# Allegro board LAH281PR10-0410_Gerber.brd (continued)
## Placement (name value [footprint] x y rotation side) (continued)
CN178  10U_0402_6.3V6M  [C_0402]  329.25 13.19 0 bottom
CN179  330U_D2E_6.3VM_R25M  [C_D2E]  311.33 15.48 180 bottom
CN180  0.22U_0201_6.3V6K  [C_0201]  381.94 12.8 270 bottom
CN181  0.22U_0201_6.3V6K  [C_0201]  381.05 12.8 270 bottom
CN182  0.22U_0201_6.3V6K  [C_0201]  378.89 12.8 270 bottom
CN183  0.22U_0201_6.3V6K  [C_0201]  378 12.8 270 bottom
CN184  0.22U_0201_6.3V6K  [C_0201]  375.97 12.8 270 bottom
CN185  0.22U_0201_6.3V6K  [C_0201]  375.08 12.8 270 bottom
CN186  0.22U_0201_6.3V6K  [C_0201]  372.92 12.8 270 bottom
CN187  0.22U_0201_6.3V6K  [C_0201]  372.03 12.8 270 bottom
CN188  10U_0402_6.3V6M  [C_0402]  360.75 9.84 90 top
CN189  10U_0402_6.3V6M  [C_0402]  361.64 9.84 90 top
CN190  0.01U_0402_16V7K  [C_0402]  364.36 10.81 0 top
CN191  0.01U_0402_16V7K  [C_0402]  367.47 10.65 180 top
CN192  0.1U_0201_10V6K  [C_0201]  355.55 9.16 180 bottom
CN193  330U_D2E_6.3VM_R25M  [C_D2E]  359.44 5.65 180 bottom
CN194  0.22U_0201_6.3V6K  [C_0201]  315.64 55.05 0 bottom
CN195  0.22U_0201_6.3V6K  [C_0201]  315.64 54.16 0 bottom
CN196  0.22U_0201_6.3V6K  [C_0201]  315.64 52.05 0 bottom
CN197  0.22U_0201_6.3V6K  [C_0201]  315.64 51.16 0 bottom
CN198  0.22U_0201_6.3V6K  [C_0201]  315.64 49.05 0 bottom
CN199  0.22U_0201_6.3V6K  [C_0201]  315.64 48.16 0 bottom
CN200  0.22U_0201_6.3V6K  [C_0201]  315.64 46.05 0 bottom
CN201  0.22U_0201_6.3V6K  [C_0201]  315.64 45.16 0 bottom
CN202  10U_0402_6.3V6M  [C_0402]  329.12 58.05 0 bottom
CN203  0.01U_0402_16V7K  [C_0402]  328.67 37.73 0 bottom
CN204  0.01U_0402_16V7K  [C_0402]  328.67 38.62 0 bottom
CN205  0.1U_0201_10V6K  [C_0201]  318.05 64.22 90 bottom
CN206  10U_0402_6.3V6M  [C_0402]  328.67 39.51 0 bottom
CN207  330U_D2E_6.3VM_R25M  [C_D2E]  314.78 64.78 90 bottom
CN208  0.22U_0201_6.3V6K  [C_0201]  137 100.82 270 bottom
CN209  0.22U_0201_6.3V6K  [C_0201]  136.11 100.82 270 bottom
CN210  0.22U_0201_6.3V6K  [C_0201]  133.98 100.82 270 bottom
CN211  0.22U_0201_6.3V6K  [C_0201]  133.09 100.82 270 bottom
CN212  0.22U_0201_6.3V6K  [C_0201]  131.49 100.82 270 bottom
CN213  0.22U_0201_6.3V6K  [C_0201]  130.6 100.82 270 bottom
CN214  0.22U_0201_6.3V6K  [C_0201]  129.11 100.64 270 bottom
CN215  0.22U_0201_6.3V6K  [C_0201]  128.51 100.62 270 bottom
CN216  10U_0402_6.3V6M  [C_0402]  120.02 87.37 270 bottom
CN217  330U_D2E_6.3VM_R25M  [C_D2E]  147.84 91.87 90 bottom
CN218  10U_0402_6.3V6M  [C_0402]  142.06 89.68 270 bottom
CN219  0.01U_0402_16V7K  [C_0402]  119.01 87.37 270 bottom
CN220  0.01U_0402_16V7K  [C_0402]  120.91 87.37 270 bottom
CN221  0.1U_0201_10V6K  [C_0201]  121.69 87.46 270 bottom
CN276  0.1U_0201_10V6K  [C_0201]  329.94 33.43 0 bottom
CN277  0.01U_0402_16V7K  [C_0402]  329.89 30.89 0 bottom
CN279  0.01U_0402_16V7K  [C_0402]  329.89 31.8 0 bottom
CN280  0.1U_0201_10V6K  [C_0201]  329.23 26.78 0 bottom
CN281  10U_0402_6.3V6M  [C_0402]  329.35 26.03 0 bottom
CN282  0.01U_0402_16V7K  [C_0402]  329.35 25.12 0 bottom
CN283  0.1U_0201_10V6K  [C_0201]  382.47 10.47 0 top
CN285  0.01U_0402_16V7K  [C_0402]  385.57 10.63 0 top
CN286  0.01U_0402_16V7K  [C_0402]  384.75 10.64 180 top
CN287  0.1U_0201_10V6K  [C_0201]  378.38 10.57 90 top
CN288  0.01U_0402_16V7K  [C_0402]  379.09 10.64 0 top
CN289  10U_0402_6.3V6M  [C_0402]  376.53 10.63 180 top
CN295  0.1U_0201_10V6K  [C_0201]  329.22 58.82 0 bottom
CN297  0.01U_0402_16V7K  [C_0402]  329.12 56.28 0 bottom
CN298  0.01U_0402_16V7K  [C_0402]  329.12 57.16 0 bottom
CN299  0.1U_0201_10V6K  [C_0201]  329.94 51.27 0 bottom
CN300  10U_0402_6.3V6M  [C_0402]  329.78 52.92 0 bottom
CN301  0.01U_0402_16V7K  [C_0402]  329.78 52.03 0 bottom
CN306  0.1U_0201_10V6K  [C_0201]  136.89 91.38 0 top
CN309  0.01U_0402_16V7K  [C_0402]  140.03 87.72 270 bottom
CN310  0.01U_0402_16V7K  [C_0402]  136.83 92.12 0 top
CN311  0.1U_0201_10V6K  [C_0201]  139.27 87.68 270 bottom
CN312  0.01U_0402_16V7K  [C_0402]  136.83 93.03 0 top
CN313  10U_0402_6.3V6M  [C_0402]  141.04 87.72 270 bottom
CR200  5P_0402_50V8C  [C_0402]  14.88 9.96 270 bottom
CR203  0.22U_0201_6.3V6K  [C_0201]  25.96 19.1 180 bottom
CR204  0.22U_0201_6.3V6K  [C_0201]  23.87 13.98 180 bottom
CR205  0.22U_0201_6.3V6K  [C_0201]  25.96 18.21 180 bottom
CR206  0.22U_0201_6.3V6K  [C_0201]  23.9 13.1 180 bottom
CR214  0.1U_0201_25V6K  [C_0201]  11.83 25.13 270 bottom
CR215  10U_0402_6.3V6M  [C_0402]  10.92 24.25 90 bottom
CR217  0.1U_0201_10V6K  [C_0201]  16.04 21.64 0 bottom
CR218  22U_0603_6.3V6M  [C_0603]  15.14 21.67 90 bottom
CR219  100P_0402_50V8J  [C_0402]  24.68 14.9 90 bottom
CR220  1U_0201_6.3V6M  [C_0201]  25.42 15.31 90 bottom
CR221  0.1U_0201_10V6K  [C_0201]  26 15.9 270 bottom
CR222  0.1U_0201_10V6K  [C_0201]  20.13 10.01 0 bottom
CR223  4.7U_0402_6.3V6M  [C_0402]  21.14 10.93 180 bottom
CR224  0.1U_0201_25V6K  [C_0201]  32.2 25.67 180 bottom
CR225  4.7U_0402_6.3V6M  [C_0402]  32.34 26.48 180 bottom
CR227  0.1U_0201_25V6K  [C_0201]  14.02 26.06 180 bottom
CR228  4.7U_0402_6.3V6M  [C_0402]  13.99 25.14 180 bottom
CR229  1U_0201_6.3V6M  [C_0201]  22.94 11.52 90 bottom
CR230  0.1U_0201_10V6K  [C_0201]  22.38 12.12 270 bottom
CR234  0.1U_0201_10V6K  [C_0201]  18.01 9.29 180 bottom
CR235  10U_0402_6.3V6M  [C_0402]  18.26 10.04 180 bottom
CR236  0.1U_0201_25V6K  [C_0201]  12.6 8.49 270 bottom
CR237  100P_0402_50V8J  [C_0402]  24.01 19.29 180 bottom
CR238  1U_0201_6.3V6M  [C_0201]  24.59 20.03 180 bottom
CR239  0.1U_0201_10V6K  [C_0201]  24.57 20.74 0 bottom
CR240  100P_0402_50V8J  [C_0402]  10.75 14.59 0 bottom
CR241  1U_0201_6.3V6M  [C_0201]  10.79 15.33 0 bottom
CR242  0.1U_0201_10V6K  [C_0201]  11.39 15.9 180 bottom
CR244  1U_0201_10V6M  [C_0201]  14.14 8.96 90 bottom
CR245  1U_0201_10V6M  [C_0201]  22.58 21.45 180 bottom
CR246  0.1U_0201_25V6K  [C_0201]  22.58 22.37 180 bottom
CR247  0.1U_0201_10V6K  [C_0201]  19.7 21.05 0 bottom
CR248  4.7U_0402_6.3V6M  [C_0402]  20.75 21.96 180 bottom
CR249  100P_0402_50V8J  [C_0402]  25.89 17.22 180 bottom
CR250  1U_0201_6.3V6M  [C_0201]  24.15 17.56 270 bottom
CR251  0.1U_0201_10V6K  [C_0201]  23.58 16.98 90 bottom
CR252  100P_0402_50V8J  [C_0402]  10.78 17.9 0 bottom
CR253  1U_0201_6.3V6M  [C_0201]  10.82 17.14 0 bottom
CR254  0.1U_0201_10V6K  [C_0201]  11.4 16.5 180 bottom
CR255  1U_0201_10V6M  [C_0201]  29.37 19.13 0 bottom
CR256  0.1U_0201_25V6K  [C_0201]  29.74 13.48 180 bottom
CT1  0.1U_0201_10V6K  [C_0201]  48.17 42.56 0 top
CT2  0.22U_0201_6.3V6K  [C_0201]  44.42 39.45 270 bottom
CT3  0.22U_0201_6.3V6K  [C_0201]  45.03 39.46 270 bottom
CT4  0.22U_0201_6.3V6K  [C_0201]  41.93 39.46 270 bottom
CT5  0.22U_0201_6.3V6K  [C_0201]  42.56 39.46 270 bottom
CT6  0.22U_0201_6.3V6K  [C_0201]  43.2 38.88 90 bottom
CT7  0.22U_0201_6.3V6K  [C_0201]  43.83 38.88 90 bottom
CT8  0.22U_0201_6.3V6K  [C_0201]  40.66 38.88 90 bottom
CT9  0.22U_0201_6.3V6K  [C_0201]  41.29 38.88 90 bottom
CT10  0.22U_0201_6.3V6K  [C_0201]  44.19 50.66 0 bottom
CT11  0.22U_0201_6.3V6K  [C_0201]  44.19 50.02 0 bottom
CT12  0.22U_0201_6.3V6K  [C_0201]  44.23 49.29 0 bottom
CT13  0.22U_0201_6.3V6K  [C_0201]  44.23 48.66 0 bottom
CT14  0.22U_0201_6.3V6K  [C_0201]  44.22 48.01 0 bottom
CT15  0.22U_0201_6.3V6K  [C_0201]  44.22 47.38 0 bottom
CT16  0.22U_0201_6.3V6K  [C_0201]  44.22 46.69 0 bottom
CT17  0.22U_0201_6.3V6K  [C_0201]  44.22 46.06 0 bottom
CT18  0.22U_0201_6.3V6K  [C_0201]  37.54 54.97 90 bottom
CT19  0.22U_0201_6.3V6K  [C_0201]  36.9 54.97 90 bottom
CT20  20P_0402_50V8  [C_0402]  31.5 38.6 0 bottom
CT21  20P_0402_50V8  [C_0402]  29.75 38.57 90 bottom
CT67  1U_0201_10V6M  [C_0201]  26.45 55.7 0 bottom
CT68  47U_0603_6.3V6M  [C_0603]  26.37 56.81 0 bottom
CT69  47U_0603_6.3V6M  [C_0603]  26.37 58.59 0 bottom
CT91  0.47U_0201_25V6M  [C_0201]  11.13 52.47 0 bottom
CT95  0.22U_0201_6.3V6K  [C_0201]  30.39 43.65 180 bottom
CT96  0.22U_0201_6.3V6K  [C_0201]  30.39 44.24 180 bottom
CT97  0.22U_0201_6.3V6K  [C_0201]  30.39 45.55 180 bottom
CT98  0.22U_0201_6.3V6K  [C_0201]  30.39 44.96 180 bottom
CT101  0.47U_0201_25V6M  [C_0201]  11.13 52.47 0 top
CT102  0.47U_0201_25V6M  [C_0201]  11.15 55.96 0 bottom
CT109  0.47U_0201_25V6M  [C_0201]  11.15 55.96 0 top
CT123  0.22U_0201_6.3V6K  [C_0201]  39.39 39.46 270 bottom
CT124  0.22U_0201_6.3V6K  [C_0201]  40.02 39.46 270 bottom
CT125  0.22U_0201_6.3V6K  [C_0201]  37.48 39.46 270 bottom
CT126  0.22U_0201_6.3V6K  [C_0201]  36.85 39.46 270 bottom
CT127  0.22U_0201_6.3V6K  [C_0201]  38.75 38.88 90 bottom
CT128  0.22U_0201_6.3V6K  [C_0201]  38.12 38.88 90 bottom
CT129  0.22U_0201_6.3V6K  [C_0201]  36.21 38.88 90 bottom
CT130  0.22U_0201_6.3V6K  [C_0201]  35.58 38.88 90 bottom
CT178  0.22U_0201_6.3V6K  [C_0201]  38.81 54.97 90 bottom
CT179  0.22U_0201_6.3V6K  [C_0201]  33.33 54.32 90 bottom
CT180  0.22U_0201_6.3V6K  [C_0201]  30.59 54.75 180 bottom
CT181  0.22U_0201_6.3V6K  [C_0201]  33.92 54.31 90 bottom
CT182  0.22U_0201_6.3V6K  [C_0201]  34.55 54.31 90 bottom
CT183  0.22U_0201_6.3V6K  [C_0201]  30.59 55.51 180 bottom
CT184  0.22U_0201_6.3V6K  [C_0201]  38.17 54.97 90 bottom
CT185  0.22U_0201_6.3V6K  [C_0201]  32.69 54.32 90 bottom
CT186  0.22U_0201_6.3V6K  [C_0201]  30.07 53.3 180 bottom
CT187  0.22U_0201_6.3V6K  [C_0201]  30.08 54 180 bottom
CT189  12P_0402_50V8J  [C_0402]  9.93 45.86 180 bottom
CT190  82P_0402_50V8J  [C_0402]  9.93 46.75 180 bottom
CT237  0.1U_0201_10V6K  [C_0201]  118.15 64.66 0 top
CT300  1U_0201_6.3V6M  [C_0201]  35.83 44.6 180 top
CT301  1U_0201_6.3V6M  [C_0201]  34.82 42.34 270 top
CT302  1U_0201_6.3V6M  [C_0201]  33.23 45.4 180 top
CT303  1U_0201_6.3V6M  [C_0201]  40.47 49.19 0 top
CT305  1U_0201_6.3V6M  [C_0201]  34.99 46.56 180 top
CT306  1U_0201_6.3V6M  [C_0201]  35.85 48.53 0 top
CT307  1U_0201_6.3V6M  [C_0201]  37.58 49.24 180 top
CT308  1U_0201_6.3V6M  [C_0201]  34.99 47.19 180 top
CT309  1U_0201_6.3V6M  [C_0201]  36.99 47.13 0 top
CT310  1U_0201_6.3V6M  [C_0201]  37.65 48.45 180 top
CT311  1U_0201_6.3V6M  [C_0201]  39.47 47.65 270 top
CT314  1U_0201_6.3V6M  [C_0201]  34.98 45.82 180 top
CT315  1U_0201_6.3V6M  [C_0201]  38.3 49.8 270 top
CT316  1U_0201_6.3V6M  [C_0201]  38.89 47.25 90 top
CT317  1U_0201_6.3V6M  [C_0201]  38.94 45.95 90 top
CT318  1U_0201_6.3V6M  [C_0201]  35.34 47.77 0 top
CT319  1U_0201_6.3V6M  [C_0201]  36.31 46.62 180 top
CT320  1U_0201_6.3V6M  [C_0201]  32.55 49.8 0 top
CT321  1U_0201_6.3V6M  [C_0201]  39.8 45.16 90 top
CT322  1U_0201_6.3V6M  [C_0201]  40.9 46.55 180 top
CT323  10U_0402_6.3V6M  [C_0402]  32.92 53.35 180 top
CT324  10U_0402_6.3V6M  [C_0402]  32.92 51.58 180 top
CT325  10U_0402_6.3V6M  [C_0402]  32.92 50.69 180 top
CT326  10U_0402_6.3V6M  [C_0402]  32.92 52.47 180 top
CT327  1U_0201_6.3V6M  [C_0201]  37.72 53.01 90 top
CT328  1U_0201_6.3V6M  [C_0201]  33.99 52.6 270 top
CT329  10U_0402_6.3V6M  [C_0402]  33.04 47.64 180 top
CT330  10U_0402_6.3V6M  [C_0402]  33.04 46.75 180 top
CT331  1U_0201_6.3V6M  [C_0201]  33.89 48.53 270 top
CT332  1U_0201_6.3V6M  [C_0201]  33.01 48.53 180 top
CT333  1U_0201_6.3V6M  [C_0201]  36.39 49.2 180 top
CT334  47U_0603_6.3V6M  [C_0603]  31.75 59.52 270 bottom
CT335  47U_0603_6.3V6M  [C_0603]  30.54 59.53 270 bottom
CT336  47U_0603_6.3V6M  [C_0603]  29.33 59.53 270 bottom
CT337  10U_0402_6.3V6M  [C_0402]  38.2 42.53 270 top
CT338  1U_0201_6.3V6M  [C_0201]  37.67 45.82 90 top
CT339  1U_0201_6.3V6M  [C_0201]  37.75 43.37 0 top
CT340  1U_0201_6.3V6M  [C_0201]  37.07 43.32 180 top
CT341  1U_0201_6.3V6M  [C_0201]  37.07 42.71 180 top
CT342  0.1U_0201_10V6K  [C_0201]  23.21 38.64 0 bottom
CT343  1U_0201_6.3V6M  [C_0201]  14.67 34.64 180 bottom
CT344  0.1U_0201_10V6K  [C_0201]  26.54 31.8 0 bottom
CT345  0.1U_0201_10V6K  [C_0201]  26.54 31.24 0 bottom
CT346  1U_0201_6.3V6M  [C_0201]  26.54 32.36 0 bottom
CT347  0.1U_0201_10V6K  [C_0201]  19.24 26.94 180 bottom
CT348  1U_0201_10V6M  [C_0201]  23.95 26.71 90 bottom
CT349  1U_0201_6.3V6M  [C_0201]  19.24 27.83 180 bottom
CT350  0.1U_0201_10V6K  [C_0201]  20.23 38.5 0 bottom
CT351  390P_0402_50V7K  [C_0402]  24.7 39.11 270 bottom
CT352  390P_0402_50V7K  [C_0402]  15.11 36.72 180 bottom
CT353  390P_0402_50V7K  [C_0402]  26.82 37.43 180 bottom
CT354  390P_0402_50V7K  [C_0402]  11.96 35.19 180 bottom
CT355  10U_0603_10V6M  [C_0603]  37.79 21.03 270 top
CT356  1U_0201_10V6M  [C_0201]  36.14 20.75 270 top
CT357  10U_0603_10V6M  [C_0603]  42.77 21.73 270 top
CT358  1U_0201_10V6M  [C_0201]  41.73 21.26 270 top
CT359  0.22U_0201_6.3V6K  [C_0201]  30.31 47.74 180 bottom
CT360  0.22U_0201_6.3V6K  [C_0201]  30.31 48.33 180 bottom
CT361  0.47U_0201_25V6M  [C_0201]  11.44 67.48 315 bottom
CT362  0.47U_0201_25V6M  [C_0201]  11.44 67.48 315 top
CT363  0.47U_0201_25V6M  [C_0201]  12.5 71.4 315 bottom
CT364  0.47U_0201_25V6M  [C_0201]  12.5 71.4 315 top
CT365  0.22U_0201_6.3V6K  [C_0201]  29.77 49.22 180 bottom
CT366  0.22U_0201_6.3V6K  [C_0201]  29.77 49.85 180 bottom
CT367  12P_0402_50V8J  [C_0402]  21.85 68.34 45 bottom
CT368  82P_0402_50V8J  [C_0402]  21.21 68.97 45 bottom
CT370  0.1U_0201_10V6K  [C_0201]  34.34 21.22 180 bottom
CT371  0.1U_0201_10V6K  [C_0201]  41.58 19.06 180 top
CT372  1U_0201_10V6M  [C_0201]  42.22 17.22 90 top
CT373  1U_0201_10V6M  [C_0201]  43.5 18.33 180 top
CT374  1000P_0402_50V7K  [C_0402]  48.52 20.59 180 top
CT375  0.01U_0402_16V7K  [C_0402]  43.55 13.87 270 top
CT376  0.1U_0201_25V6K  [C_0201]  44.43 15.51 90 top
CT377  0.1U_0201_10V6K  [C_0201]  40.61 24.81 180 bottom
CT378  1000P_0201_25V7K  [C_0201]  38.86 26.09 90 bottom
CT379  0.1U_0201_10V6K  [C_0201]  47.6 23.54 0 bottom
CT380  1000P_0201_25V7K  [C_0201]  45.07 26.65 90 bottom
CT383  0.1U_0201_10V6K  [C_0201]  40.05 24.04 0 bottom
CT384  0.1U_0201_10V6K  [C_0201]  47.27 25.5 270 bottom
CT389  0.1U_0201_10V6K  [C_0201]  118.37 61.58 270 top
CV1  0.1U_0201_10V6K  [C_0201]  126.31 133.47 270 top
CV2  0.1U_0201_10V6K  [C_0201]  127.2 133.47 270 top
CV3  0.1U_0201_10V6K  [C_0201]  128.62 133.49 270 top
CV4  0.1U_0201_10V6K  [C_0201]  129.51 133.49 270 top
CV5  0.1U_0201_10V6K  [C_0201]  130.63 133.47 270 top
CV6  0.1U_0201_10V6K  [C_0201]  131.52 133.47 270 top
CV13  1U_0603_50V6K  [C_0603]  141.17 135.52 270 top
CV14  0.01U_0402_50V7K  [C_0402]  141.69 137.04 180 top
CV15  0.1U_0402_50V7K  [C_0402]  142.59 131.59 180 top
CV16  10U_0402_6.3V6M  [C_0402]  110.93 148.99 0 bottom
CV20  0.1U_0201_25V6K  [C_0201]  113.33 119.78 180 bottom
CV60  0.01U_0402_16V7K  [C_0402]  304.06 81.42 180 bottom
CV61  0.01U_0402_16V7K  [C_0402]  294.26 81.68 0 bottom
CV62  0.1U_0201_25V6K  [C_0201]  304.06 78.12 180 bottom
CV63  0.1U_0201_25V6K  [C_0201]  296.82 77.74 180 bottom
CV64  0.1U_0201_25V6K  [C_0201]  294.84 79.21 270 bottom
CV65  0.1U_0201_10V6K  [C_0201]  296.06 74.6 90 top
CV66  0.1U_0201_10V6K  [C_0201]  296.95 74.6 90 top
CV67  0.1U_0201_10V6K  [C_0201]  297.89 74.6 90 top
CV68  0.1U_0201_10V6K  [C_0201]  298.78 74.6 90 top
CV69  0.1U_0201_10V6K  [C_0201]  299.74 74.63 90 top
CV70  0.1U_0201_10V6K  [C_0201]  300.63 74.63 90 top
CV71  0.1U_0201_10V6K  [C_0201]  301.6 74.63 90 top
CV72  0.1U_0201_10V6K  [C_0201]  302.49 74.65 90 top
CV73  0.1U_0201_10V6K  [C_0201]  305.76 77.66 90 top
CV74  0.1U_0201_10V6K  [C_0201]  306.65 77.66 90 top
CV75  2.2U_0402_6.3V6M  [C_0402]  303.43 75.54 270 top
CV427  0.22U_0201_6.3V6K  [C_0201]  237.55 77.73 270 bottom
CV428  0.22U_0201_6.3V6K  [C_0201]  236.64 77.73 270 bottom
CV429  0.22U_0201_6.3V6K  [C_0201]  238.73 75.9 270 bottom
CV430  0.22U_0201_6.3V6K  [C_0201]  237.83 75.9 270 bottom
CV431  0.22U_0201_6.3V6K  [C_0201]  239.8 77.85 270 bottom
CV432  0.22U_0201_6.3V6K  [C_0201]  238.91 77.85 270 bottom
CV433  0.22U_0201_6.3V6K  [C_0201]  240.01 75.14 270 bottom
CV434  0.22U_0201_6.3V6K  [C_0201]  240.9 75.14 270 bottom
CV435  0.22U_0201_6.3V6K  [C_0201]  242.01 77.56 270 bottom
CV436  0.22U_0201_6.3V6K  [C_0201]  241.12 77.56 270 bottom
CV437  0.22U_0201_6.3V6K  [C_0201]  242.26 75.15 270 bottom
CV438  0.22U_0201_6.3V6K  [C_0201]  243.15 75.15 270 bottom
CV439  0.22U_0201_6.3V6K  [C_0201]  244.29 77.18 270 bottom
CV440  0.22U_0201_6.3V6K  [C_0201]  243.41 77.18 270 bottom
CV441  0.22U_0201_6.3V6K  [C_0201]  244.55 74.39 270 bottom
CV442  0.22U_0201_6.3V6K  [C_0201]  245.44 74.39 270 bottom
CV443  0.22U_0201_6.3V6K  [C_0201]  246.83 74.39 270 bottom
CV444  0.22U_0201_6.3V6K  [C_0201]  247.72 74.39 270 bottom
CV445  0.22U_0201_6.3V6K  [C_0201]  245.69 76.58 270 bottom
CV446  0.22U_0201_6.3V6K  [C_0201]  246.6 76.58 270 bottom
CV447  0.22U_0201_6.3V6K  [C_0201]  247.98 76.55 270 bottom
CV448  0.22U_0201_6.3V6K  [C_0201]  248.87 76.55 270 bottom
CV449  0.22U_0201_6.3V6K  [C_0201]  250.01 74.51 270 bottom
CV450  0.22U_0201_6.3V6K  [C_0201]  249.12 74.51 270 bottom
CV451  0.22U_0201_6.3V6K  [C_0201]  250.26 76.55 270 bottom
CV452  0.22U_0201_6.3V6K  [C_0201]  251.15 76.55 270 bottom
CV453  0.22U_0201_6.3V6K  [C_0201]  253.18 74.64 270 bottom
CV454  0.22U_0201_6.3V6K  [C_0201]  254.07 74.64 270 bottom
CV455  0.22U_0201_6.3V6K  [C_0201]  251.41 74.64 270 bottom
CV456  0.22U_0201_6.3V6K  [C_0201]  252.3 74.64 270 bottom
CV457  0.22U_0201_6.3V6K  [C_0201]  255.9 75.61 270 bottom
CV458  0.22U_0201_6.3V6K  [C_0201]  255.01 75.61 270 bottom
CV805  0.1U_0201_16V6K  [C_0201]  236.57 92.79 0 bottom
CV806  10U_0402_6.3V6M  [C_0402]  252.21 84.05 180 top
CV809  0.1U_0201_10V6K  [C_0201]  291.79 77.87 90 bottom
CV810  0.1U_0201_10V6K  [C_0201]  286 84.61 0 bottom
CV811  0.1U_0201_10V6K  [C_0201]  279.51 82.56 180 bottom
CV812  1000P_0402_50V7K  [C_0402]  287.26 76.59 180 bottom
CV813  4.7U_0402_6.3V6M  [C_0402]  150.9 123.59 180 top
CV814  0.1U_0201_10V6K  [C_0201]  149.93 117.68 90 bottom
CV815  0.1U_0201_10V6K  [C_0201]  160.08 119.33 90 bottom
CV816  0.1U_0201_10V6K  [C_0201]  161.37 117.51 0 top
CV817  0.1U_0201_10V6K  [C_0201]  156.47 121.85 270 bottom
CV818  2.2U_0402_6.3V6M  [C_0402]  152.81 125.77 270 top
CV819  0.1U_0201_10V6K  [C_0201]  155.16 113.11 90 top
CV820  0.1U_0201_10V6K  [C_0201]  156.05 113.11 90 top
CV821  0.1U_0201_10V6K  [C_0201]  156.69 110.82 90 top
CV822  0.1U_0201_10V6K  [C_0201]  157.58 110.82 90 top
CV823  0.1U_0201_10V6K  [C_0201]  158.03 113.24 90 top
CV824  0.1U_0201_10V6K  [C_0201]  158.97 113.24 90 top
CV825  0.1U_0201_10V6K  [C_0201]  159.53 110.95 90 top
CV826  0.1U_0201_10V6K  [C_0201]  160.42 110.95 90 top
CV827  0.1U_0201_10V6K  [C_0201]  163.37 122.2 180 top
CV828  0.1U_0201_10V6K  [C_0201]  163.37 121.31 180 top
CV829  0.1U_0201_10V6K  [C_0201]  149.53 113.11 90 top
CV830  0.1U_0201_10V6K  [C_0201]  150.41 113.11 90 top
CV831  0.1U_0201_10V6K  [C_0201]  150.59 110.7 90 top
CV832  0.1U_0201_10V6K  [C_0201]  151.48 110.7 90 top
CV833  0.1U_0201_10V6K  [C_0201]  152.34 112.98 90 top
CV834  0.1U_0201_10V6K  [C_0201]  153.26 112.98 90 top
CV835  0.1U_0201_10V6K  [C_0201]  153.64 110.7 90 top
CV836  0.1U_0201_10V6K  [C_0201]  154.53 110.7 90 top
CV837  0.1U_0201_10V6K  [C_0201]  163.37 120.42 180 top
CV838  0.1U_0201_10V6K  [C_0201]  163.37 119.53 180 top
CV839  82P_0402_50V8J  [C_0402]  141.68 132.54 0 top
CV840  82P_0402_50V8J  [C_0402]  113.94 116.28 180 top
CV841  22P_0402_50V8J  [C_0402]  113.94 115.33 180 top
CV842  100P_0402_50V8J  [C_0402]  125.98 110 0 top
CV843  100P_0402_50V8J  [C_0402]  126.95 111.32 90 top
CV844  0.1U_0201_10V6K  [C_0201]  163.98 125.16 270 top
CV845  0.1U_0201_10V6K  [C_0201]  132.53 133.47 270 top
CV846  0.1U_0201_10V6K  [C_0201]  133.42 133.47 270 top
CV847  0.1U_0201_10V6K  [C_0201]  134.44 133.47 270 top
CV848  0.1U_0201_10V6K  [C_0201]  135.33 133.47 270 top
CV849  0.1U_0402_50V7K  [C_0402]  114.82 115.42 90 top
CV851  10P_0402_50V8J  [C_0402]  112.65 120.66 0 bottom
CV852  82P_0402_50V8J  [C_0402]  117.09 120.54 0 bottom
CV853  2.2P_0402_50V8C  [C_0402]  113.56 121.55 180 bottom
CV854  4.7U_0402_6.3V6M  [C_0402]  63.32 56.33 90 top
CV855  0.1U_0201_10V6K  [C_0201]  61.36 56.56 90 top
CV856  0.1U_0201_10V6K  [C_0201]  62.26 56.56 90 top
CV857  0.01U_0402_16V7K  [C_0402]  59.56 56.38 90 top
CV858  0.01U_0402_16V7K  [C_0402]  60.46 56.39 90 top
CV860  0.22U_0201_6.3V6K  [C_0201]  60.87 53.61 0 bottom
CV861  0.22U_0201_6.3V6K  [C_0201]  60.87 52.97 0 bottom
CV862  0.22U_0201_6.3V6K  [C_0201]  60.87 52.34 0 bottom
CV863  0.22U_0201_6.3V6K  [C_0201]  60.87 51.7 0 bottom
CV864  0.22U_0201_6.3V6K  [C_0201]  60.36 50.94 0 bottom
CV865  0.22U_0201_6.3V6K  [C_0201]  60.36 50.31 0 bottom
CV866  0.22U_0201_6.3V6K  [C_0201]  61.63 49.93 0 bottom
CV867  0.22U_0201_6.3V6K  [C_0201]  61.63 49.29 0 bottom
CV868  0.22U_0201_6.3V6K  [C_0201]  60.36 48.91 0 bottom
CV869  0.22U_0201_6.3V6K  [C_0201]  60.36 48.27 0 bottom
CV870  0.22U_0201_6.3V6K  [C_0201]  60.23 47.13 0 bottom
CV871  0.22U_0201_6.3V6K  [C_0201]  60.23 46.5 0 bottom
CV872  0.22U_0201_6.3V6K  [C_0201]  63.41 45.73 0 bottom
CV873  0.22U_0201_6.3V6K  [C_0201]  63.41 45.1 0 bottom
CV874  0.22U_0201_6.3V6K  [C_0201]  60.23 44.72 0 bottom
CV875  0.22U_0201_6.3V6K  [C_0201]  60.23 44.08 0 bottom
CV876  0.1U_0201_10V6K  [C_0201]  55.06 56.95 270 bottom
CV877  0.1U_0201_10V6K  [C_0201]  54.43 56.95 270 bottom
CV878  4.7U_0402_6.3V6M  [C_0402]  68.16 42.14 90 top
CV879  0.1U_0201_10V6K  [C_0201]  67.13 42.33 90 top
CV880  0.1U_0201_10V6K  [C_0201]  69.16 42.33 90 top
CV881  0.01U_0402_16V7K  [C_0402]  68.66 44.5 180 top
CV882  0.01U_0402_16V7K  [C_0402]  69.67 47.69 90 top
CV883  0.22U_0201_6.3V6K  [C_0201]  70.81 45.39 270 top
CV884  0.22U_0201_6.3V6K  [C_0201]  71.45 45.39 270 top
CV885  0.22U_0201_6.3V6K  [C_0201]  72.97 45.77 270 top
CV886  0.22U_0201_6.3V6K  [C_0201]  73.61 45.77 270 top
CV887  0.22U_0201_6.3V6K  [C_0201]  74.24 45.77 270 top
CV888  0.22U_0201_6.3V6K  [C_0201]  74.88 45.77 270 top
CV889  0.22U_0201_6.3V6K  [C_0201]  75.51 45.77 270 top
CV890  0.22U_0201_6.3V6K  [C_0201]  76.15 45.77 270 top
CV891  0.22U_0201_6.3V6K  [C_0201]  76.78 45.77 270 top
CV892  0.22U_0201_6.3V6K  [C_0201]  77.42 45.77 270 top
CV893  0.22U_0201_6.3V6K  [C_0201]  78.18 45.77 270 top
CV894  0.22U_0201_6.3V6K  [C_0201]  78.81 45.77 270 top
CV895  0.22U_0201_6.3V6K  [C_0201]  79.7 45.77 270 top
CV896  0.22U_0201_6.3V6K  [C_0201]  80.34 45.77 270 top
CV897  0.22U_0201_6.3V6K  [C_0201]  80.97 45.77 270 top
CV898  0.22U_0201_6.3V6K  [C_0201]  81.61 45.77 270 top
CV901  0.01U_0402_16V7K  [C_0402]  49.19 41.69 270 bottom
CV902  10U_0402_6.3V6M  [C_0402]  247.65 83.82 180 top
CV903  0.1U_0201_10V6K  [C_0201]  230.87 94.25 180 bottom
CV908  0.1U_0201_10V6K  [C_0201]  62.75 56.56 90 bottom
CV909  0.1U_0201_10V6K  [C_0201]  59.7 42.53 270 bottom
CV910  4.7U_0402_6.3V6M  [C_0402]  63.7 56.53 0 bottom
CV911  0.01U_0402_16V7K  [C_0402]  52.77 48.58 0 top
CV912  0.01U_0402_16V7K  [C_0402]  52.7 54.37 0 top
CV913  0.1U_0201_10V6K  [C_0201]  52.93 53.42 0 top
CV914  4.7U_0402_6.3V6M  [C_0402]  52.7 55.45 0 top
CV915  0.1U_0201_10V6K  [C_0201]  52.8 47.7 0 top
CV916  0.01U_0402_16V7K  [C_0402]  52.53 45.61 0 top
CV917  1U_0201_10V6M  [C_0201]  52.99 44.59 0 top
CV918  0.1U_0201_10V6K  [C_0201]  52.8 46.5 0 top
CV919  4.7U_0402_6.3V6M  [C_0402]  52.67 43.32 0 top
CV920  0.01U_0402_16V7K  [C_0402]  82.93 53.08 0 top
CV921  0.01U_0402_16V7K  [C_0402]  69.1 55.42 180 top
CV922  0.1U_0201_10V6K  [C_0201]  85.89 55.26 0 top
CV923  0.1U_0201_10V6K  [C_0201]  69.07 56.28 180 top
CV924  4.7U_0402_6.3V6M  [C_0402]  86.81 56.39 90 top
CV925  0.01U_0402_16V7K  [C_0402]  82.8 46.24 0 top
CV926  0.01U_0402_16V7K  [C_0402]  82.8 47.13 0 top
CV927  0.1U_0201_10V6K  [C_0201]  71.78 45.79 270 bottom
CV928  4.7U_0402_6.3V6M  [C_0402]  69.75 45.93 270 bottom
CV929  0.1U_0201_10V6K  [C_0201]  70.76 45.79 270 bottom
CV930  0.01U_0402_16V7K  [C_0402]  78.33 56.45 90 top
CV931  0.01U_0402_16V7K  [C_0402]  79.23 56.47 90 top
CV932  0.1U_0201_10V6K  [C_0201]  67.05 56.62 180 bottom
CV933  4.7U_0402_6.3V6M  [C_0402]  68.85 56.15 0 bottom
CV934  0.1U_0201_10V6K  [C_0201]  67.1 57.86 180 bottom
CV935  0.01U_0402_16V7K  [C_0402]  70.09 54.63 270 bottom
CV936  4.7U_0402_6.3V6M  [C_0402]  68.97 54.66 270 bottom
CV937  0.1U_0201_10V6K  [C_0201]  71.9 54.61 270 bottom
CV938  1U_0201_10V6M  [C_0201]  70.99 54.61 270 bottom
CV939  0.1U_0201_10V6K  [C_0201]  58.44 56.16 0 bottom
CV940  1U_0201_10V6M  [C_0201]  58.47 57.05 0 bottom
CV941  0.1U_0201_10V6K  [C_0201]  68.79 47.88 90 top
CV942  1U_0201_10V6M  [C_0201]  67.85 47.88 90 top
CV943  0.1U_0201_10V6K  [C_0201]  67.94 50.43 0 top
CV944  0.1U_0201_10V6K  [C_0201]  67.94 49.54 0 top
CV945  0.1U_0201_10V6K  [C_0201]  56.33 56.95 270 bottom
CV946  0.1U_0201_10V6K  [C_0201]  55.7 56.95 270 bottom
CV947  0.01U_0402_16V7K  [C_0402]  51.22 41.69 270 bottom
CV948  0.1U_0201_10V6K  [C_0201]  50.24 41.39 270 bottom
CV949  0.01U_0402_16V7K  [C_0402]  61.87 56.31 90 bottom
CV950  4.7U_0402_6.3V6M  [C_0402]  50.84 54.6 90 bottom
CV951  0.1U_0201_10V6K  [C_0201]  51.83 54.71 90 bottom
CV952  0.01U_0402_16V7K  [C_0402]  60.99 56.31 90 bottom
CV954  0.1U_0201_25V6K  [C_0201]  136.41 131.59 0 bottom
CV955  82P_0402_50V8J  [C_0402]  155.56 121.97 270 bottom
CV956  82P_0402_50V8J  [C_0402]  248.59 83.82 0 top
CV957  82P_0402_50V8J  [C_0402]  253.24 83.66 0 top
CZ10  0.1U_0201_10V6K  [C_0201]  156.43 102.82 90 bottom
CZ11  0.1U_0201_10V6K  [C_0201]  157.32 102.82 90 bottom
CZ12  0.1U_0201_25V6K  [C_0201]  119.05 101.42 90 bottom
CZ13  0.1U_0201_25V6K  [C_0201]  119.94 101.42 90 bottom
CZ17  0.047U_0201_10V6K  [C_0201]  143.23 116.86 90 bottom
CZ18  0.047U_0201_10V6K  [C_0201]  144.12 116.86 90 bottom
CZ19  33P_0402_50V8J  [C_0402]  163.42 116.54 90 bottom
CZ20  22U_0603_6.3V6M  [C_0603]  165.07 116.55 90 top
CZ21  33P_0402_50V8J  [C_0402]  164.31 116.54 90 bottom
CZ28  0.1U_0201_10V6K  [C_0201]  153.51 99.52 90 bottom
CZ29  0.1U_0201_10V6K  [C_0201]  154.4 99.52 90 bottom
CZ37  1U_0201_10V6M  [C_0201]  122.35 160.96 180 bottom
CZ38  33P_0402_50V8J  [C_0402]  127.96 161.98 0 bottom
CZ39  33P_0402_50V8J  [C_0402]  127.96 160.7 0 bottom
CZ40  33P_0402_50V8J  [C_0402]  124.29 160.96 180 bottom
CZ50  0.1U_0201_25V6K  [C_0201]  144.12 18.81 0 bottom
CZ51  0.1U_0201_10V6K  [C_0201]  145.62 21.39 270 bottom
CZ52  10U_0402_6.3V6M  [C_0402]  146.53 21.65 270 bottom
CZ53  0.1U_0201_10V6K  [C_0201]  136.81 17.67 0 top
CZ54  0.1U_0201_10V6K  [C_0201]  136.81 17.03 0 top
CZ55  10U_0603_10V6M  [C_0603]  137.35 18.56 0 top
CZ56  0.1U_0201_25V6K  [C_0201]  134.34 15.62 0 bottom
CZ57  12P_0402_50V8J  [C_0402]  150.78 23.76 0 bottom
CZ58  68P_0402_50V8J  [C_0402]  150.78 24.65 0 bottom
CZ59  12P_0402_50V8J  [C_0402]  147.71 18.98 0 bottom
CZ60  68P_0402_50V8J  [C_0402]  147.73 19.89 0 bottom
CZ61  0.047U_0201_10V6K  [C_0201]  339.88 47.89 0 top
CZ62  68P_0402_50V8J  [C_0402]  338.15 54.8 90 top
CZ63  68P_0402_50V8J  [C_0402]  335.28 53.48 0 bottom
CZ64  0.1U_0201_10V6K  [C_0201]  337.59 50.88 90 top
CZ66  0.1U_0201_10V6K  [C_0201]  337.5 48.63 0 top
CZ67  0.1U_0201_10V6K  [C_0201]  337.84 50.14 270 top
CZ68  0.1U_0201_10V6K  [C_0201]  337.41 53.08 90 top
CZ69  68P_0402_50V8J  [C_0402]  339.17 51.31 0 top
CZ71  68P_0402_50V8J  [C_0402]  337.18 48.53 0 bottom
CZ72  68P_0402_50V8J  [C_0402]  339.37 49.88 0 top
CZ73  68P_0402_50V8J  [C_0402]  337.56 52.21 0 top
CZ75  10U_0402_6.3V6M  [C_0402]  143.99 17.07 0 bottom
CZ80  10P_0402_50V8J  [C_0402]  29.24 12.24 0 bottom
CZ81  10P_0402_50V8J  [C_0402]  29.14 8.24 0 bottom
CZ82  0.1U_0201_10V6K  [C_0201]  106.91 13.29 90 bottom
CZ90  0.1U_0201_25V6K  [C_0201]  17.65 7.76 0 bottom
CZ91  0.1U_0201_25V6K  [C_0201]  15.59 7.46 180 bottom
CZ92  0.1U_0201_25V6K  [C_0201]  13.2 4.79 270 bottom
CZ93  0.1U_0201_10V6K  [C_0201]  388.33 6.16 180 top
CZ100  1U_0201_10V6M  [C_0201]  278.65 73.27 270 bottom
CZ101  0.1U_0201_10V6K  [C_0201]  273.38 73.08 270 bottom
CZ102  1U_0201_10V6M  [C_0201]  164.06 30.85 180 bottom
CZ105  1U_0201_10V6M  [C_0201]  269.19 79.48 90 top
CZ106  0.1U_0201_10V6K  [C_0201]  272.2 82.31 0 top
CZ120  0.1U_0201_10V6K  [C_0201]  335.46 15.51 180 top
CZ121  470P_0402_50V7K  [C_0402]  336.98 12.84 270 top
CZ129  0.1U_0201_10V6K  [C_0201]  366.51 14.14 180 top
CZ130  470P_0402_50V7K  [C_0402]  365.05 11.81 180 bottom
CZ157  330U_D2E_6.3VM_R25M  [C_D2E]  113.74 112.54 0 top
CZ164  330U_D2E_6.3VM_R25M  [C_D2E]  168.6 117.37 270 top
CZ198  100P_0402_50V8J  [C_0402]  144.71 118.57 0 bottom
CZ199  0.1U_0201_10V6K  [C_0201]  162.84 36.31 180 bottom
CZ200  0.1U_0201_10V6K  [C_0201]  152.41 19.28 270 bottom
CZ218  2.2U_0201_6.3V6M  [C_0201]  99.77 62.02 90 top
CZ505  10U_0402_6.3V6M  [C_0402]  303.73 71.32 180 top
CZ506  10U_0402_6.3V6M  [C_0402]  122.11 77.87 0 top
CZ507  0.1U_0201_25V6K  [C_0201]  122.53 78.95 0 top
CZ508  0.1U_0201_25V6K  [C_0201]  303.58 72.4 180 top
CZ509  0.1U_0201_25V6K  [C_0201]  137.68 130.22 90 bottom
CZ510  10U_0402_6.3V6M  [C_0402]  116.61 115.52 180 top
CZ511  0.1U_0201_25V6K  [C_0201]  117.76 116.28 0 top
CZ512  10P_0402_50V8J  [C_0402]  118.39 115.33 180 top
CZ513  0.1U_0201_10V6K  [C_0201]  297.15 65.1 0 top
CZ514  0.1U_0201_10V6K  [C_0201]  92.3 55.51 0 top
CZ515  470P_0402_50V7K  [C_0402]  92.81 59.15 180 top
CZ516  470P_0402_50V7K  [C_0402]  294.56 68.09 0 top
CZ517  470P_0402_50V7K  [C_0402]  294.56 67.2 0 top
CZ518  0.1U_0201_10V6K  [C_0201]  297.03 69.74 0 top
CZ519  0.1U_0201_10V6K  [C_0201]  370.41 37.44 90 top
CZ520  0.1U_0201_10V6K  [C_0201]  141.59 19.45 180 top
CZ521  470P_0402_50V7K  [C_0402]  142.52 13.98 180 top
CZ522  1000P_0402_50V7K  [C_0402]  370.85 34.04 180 top
CZ523  470P_0402_50V7K  [C_0402]  370.85 34.93 180 top
CZ524  0.1U_0201_10V6K  [C_0201]  369.45 31.8 270 top
CZ525  0.1U_0201_25V6K  [C_0201]  133.45 98.63 0 top
CZ526  0.47U_0402_25V6K  [C_0402]  130.91 87.52 180 top
CZ527  0.1U_0201_10V6K  [C_0201]  396.73 13.93 180 bottom
CZ528  82P_0402_50V8J  [C_0402]  296.92 70.68 0 top
CZ529  82P_0402_50V8J  [C_0402]  296.92 64.25 0 top
CZ530  0.1U_0201_10V6K  [C_0201]  110.46 115.09 90 bottom
CZ531  10U_0402_6.3V6M  [C_0402]  111.21 115.1 90 bottom
CZ532  0.01U_0402_16V7K  [C_0402]  129.32 115.04 90 bottom
CZ533  0.01U_0402_16V7K  [C_0402]  128.43 115.04 90 bottom
CZ534  0.1U_0201_10V6K  [C_0201]  127.7 114.94 90 bottom
CZ535  10U_0402_6.3V6M  [C_0402]  110.96 113.62 180 top
CZ536  0.1U_0201_25V6K  [C_0201]  126.57 101.67 90 bottom
CZ537  0.1U_0201_25V6K  [C_0201]  125.68 101.67 90 bottom
CZ538  0.1U_0201_25V6K  [C_0201]  124.79 101.67 90 bottom
CZ539  0.1U_0201_25V6K  [C_0201]  123.9 101.67 90 bottom
CZ540  0.1U_0201_10V6K  [C_0201]  363.23 12.82 270 bottom
CZ541  100P_0402_50V8J  [C_0402]  357.6 53.3 270 top
CZ542  0.01U_0402_16V7K  [C_0402]  111.4 112.66 180 top
CZ543  0.01U_0402_16V7K  [C_0402]  111.43 111.75 180 top
CZ544  0.1U_0201_25V6K  [C_0201]  274.37 73.48 180 top
CZ545  82P_0402_50V8J  [C_0402]  133.28 97.86 0 top
DA1  AZ5125-02S.R7G_SOT23-3  [AZ5125-02SPR7G_SOT23-3]  391.72 24.65 270 top
DA2  AZ5125-02S.R7G_SOT23-3  [AZ5125-02SPR7G_SOT23-3]  393.8 20.59 90 top
DA3  AZ5123-02S.R7G_SOT23-3  [AZ5123-02SPR7G_SOT23-3]  393.8 16.65 90 top
DA6  AZ5125-02S.R7G_SOT23-3  [AZ5125-02SPR7G_SOT23-3]  345.64 16.33 0 top
DA7  AZ5125-02S.R7G_SOT23-3  [AZ5125-02SPR7G_SOT23-3]  349.61 16.3 0 top
DA8  -  [RB751S-40_SOD523-2]  373.96 27.75 0 top
DE2  -  [RB751S-40_SOD523-2]  144 83.71 0 top
DH1  -  [RB751S-40_SOD523-2]  123.5 15.65 180 top
DH2  -  [RB751S-40_SOD523-2]  121.17 14.12 0 top
DI1  -  [AZ1045-04F_DFN2510P10E-10-9]  389.48 55.89 270 bottom
DI2  -  [PESD5V0U2BT_SOT23-3]  391.51 64.04 90 top
DI3  -  [PESD5V0U2BT_SOT23-3]  391.28 36.73 90 top
DI4  -  [AZ1045-04F_DFN2510P10E-10-9]  111.87 157.32 0 top
DI5  -  [PESD5V0U2BT_SOT23-3]  119.73 159.77 180 top
DI6  -  [AZ1045-04F_DFN2510P10E-10-9]  391.82 43.95 270 bottom
DT1  -  [SDMP0340LAT-7-F_SOT-523-3]  20.98 52.4 90 bottom
DT2  -  [SDMP0340LAT-7-F_SOT-523-3]  19.9 54.12 270 top
DT3  -  [SDMP0340LAT-7-F_SOT-523-3]  15.19 60.17 0 bottom
DT4  AZ4024_02S_R7G_SOT23-3  [PESD24VS2UT_SOT23-3]  14.58 48.02 270 bottom
DT5  AZ5B75-01B.R7G_CSP0603P2Y2  [AZ5B75-01BPR7G_CSP0603P2Y2]  16.76 49.4 270 bottom
DT6  AZ5B75-01B.R7G_CSP0603P2Y2  [AZ5B75-01BPR7G_CSP0603P2Y2]  16.76 50.09 90 bottom
DT7  -  [AZ1045-04F_DFN2510P10E-10-9]  12.26 53.19 90 bottom
DT8  -  [AZ1045-04F_DFN2510P10E-10-9]  13.14 53.19 90 top
DT9  AZ5B75-01B.R7G_CSP0603P2Y2  [AZ5B75-01BPR7G_CSP0603P2Y2]  12.32 57.19 270 bottom
DT10  AZ5B75-01B.R7G_CSP0603P2Y2  [AZ5B75-01BPR7G_CSP0603P2Y2]  12.32 57.89 90 bottom
DT11  -  [AZ1045-04F_DFN2510P10E-10-9]  14.09 66.15 0 bottom
DT12  -  [AZ1045-04F_DFN2510P10E-10-9]  14.09 65.28 0 top
DT13  AZ5B75-01B.R7G_CSP0603P2Y2  [AZ5B75-01BPR7G_CSP0603P2Y2]  16.76 49.4 270 top
DT14  AZ5B75-01B.R7G_CSP0603P2Y2  [AZ5B75-01BPR7G_CSP0603P2Y2]  16.76 50.09 90 top
DT16  -  [SDMP0340LAT-7-F_SOT-523-3]  18.57 60.97 270 top
DT17  AZ5B75-01B.R7G_CSP0603P2Y2  [AZ5B75-01BPR7G_CSP0603P2Y2]  12.32 57.89 90 top
DT18  AZ5B75-01B.R7G_CSP0603P2Y2  [AZ5B75-01BPR7G_CSP0603P2Y2]  12.32 57.19 270 top
DT43  AZ5B75-01B.R7G_CSP0603P2Y2  [AZ5B75-01BPR7G_CSP0603P2Y2]  11.21 64.64 180 bottom
DT44  AZ5B75-01B.R7G_CSP0603P2Y2  [AZ5B75-01BPR7G_CSP0603P2Y2]  11.21 64.64 180 top
DT45  AZ5B75-01B.R7G_CSP0603P2Y2  [AZ5B75-01BPR7G_CSP0603P2Y2]  11.91 64.64 0 top
DT48  AZ5B75-01B.R7G_CSP0603P2Y2  [AZ5B75-01BPR7G_CSP0603P2Y2]  11.91 64.64 0 bottom
DT51  AZ5B75-01B.R7G_CSP0603P2Y2  [AZ5B75-01BPR7G_CSP0603P2Y2]  14.87 73.19 270 bottom
DT52  AZ5B75-01B.R7G_CSP0603P2Y2  [AZ5B75-01BPR7G_CSP0603P2Y2]  14.87 73.89 90 top
DT53  AZ5B75-01B.R7G_CSP0603P2Y2  [AZ5B75-01BPR7G_CSP0603P2Y2]  14.87 73.89 90 bottom
DT54  AZ5B75-01B.R7G_CSP0603P2Y2  [AZ5B75-01BPR7G_CSP0603P2Y2]  14.87 73.19 270 top
DT59  AZ4024_02S_R7G_SOT23-3  [PESD24VS2UT_SOT23-3]  21.99 65.01 135 bottom
DT60  -  [RB520SM-30T2R_EMD2-2]  48.63 25.45 90 top
DT62  -  [RB520SM-30T2R_EMD2-2]  47.43 25.44 90 top
DT63  -  [RB520SM-30T2R_EMD2-2]  48.69 23.47 270 top
DT64  -  [RB520SM-30T2R_EMD2-2]  47.42 23.47 270 top
DT2001  -  [SBR1A20T5-7_SOD523-2-2]  15.78 51.77 0 top
DT2002  -  [SBR1A20T5-7_SOD523-2-2]  14.97 55.77 0 bottom
DT2003  -  [SBR1A20T5-7_SOD523-2-2]  15.1 55.89 0 top
DT2004  -  [SBR1A20T5-7_SOD523-2-2]  15.29 52.59 0 bottom
DT2005  -  [SBR1A20T5-7_SOD523-2-2]  13.6 63.6 270 bottom
DT2006  -  [SBR1A20T5-7_SOD523-2-2]  17.16 64.36 270 bottom
DT2007  -  [SBR1A20T5-7_SOD523-2-2]  17.16 64.3 270 top
DT2008  -  [SBR1A20T5-7_SOD523-2-2]  13.47 63.6 270 top
DV3  -  [BAT54CW_SOT323-3]  117.04 144.54 90 top
DV4  AZ5125-02S.R7G_SOT23-3  [AZ5125-02SPR7G_SOT23-3]  125.19 111.52 90 top
DV32  -  [RB751VM-40TE-17_SOD323-2]  290.52 80.79 180 bottom
DV33  -  [RB751VM-40TE-17_SOD323-2]  291.69 73.7 180 bottom
DV34  -  [RB751VM-40TE-17_SOD323-2]  286.84 80.58 270 bottom
DV35  -  [RB751VM-40TE-17_SOD323-2]  167.73 129.01 90 top
DV36  -  [RB751VM-40TE-17_SOD323-2]  169.39 129.01 90 top
DV37  -  [RB751VM-40TE-17_SOD323-2]  166.08 129.01 90 top
DV38  -  [RB751VM-40TE-17_SOD323-2]  163.05 129.17 180 top
DV39  -  [RB751VM-40TE-17_SOD323-2]  167.76 125.5 270 top
DV40  -  [RB751VM-40TE-17_SOD323-2]  163.05 130.82 180 top
DV41  -  [PESD5V0U2BT_SOT23-3]  125.87 114.7 270 top
DV42  -  [RB751VM-40TE-17_SOD323-2]  115.58 144.7 90 top
DV43  -  [RB751VM-40TE-17_SOD323-2]  223.45 82.12 0 top
DV44  -  [RB751VM-40TE-17_SOD323-2]  230.83 83.07 0 bottom
DZ1  -  [RB751S-40_SOD523-2]  124.86 117.03 270 bottom
DZ2  -  [RB751S-40_SOD523-2]  123.64 117.03 270 bottom
DZ5  -  [RB751S-40_SOD523-2]  147.65 117.94 270 bottom
DZ6  -  [RB751S-40_SOD523-2]  148.85 117.92 270 bottom
DZ8  -  [RB751S-40_SOD523-2]  338.12 46.01 0 top
DZ9  -  [BAT54CW_SOT323-3]  149.15 98.79 270 top
DZ12  -  [RB751S40T1G_SOD523-2]  98.97 63.32 180 top
DZ20  BZX384-B5V6 SC76-2  [RB751V40_SC76-2]  304.75 69.61 180 top
DZ21  BZX384-B5V6 SC76-2  [RB751V40_SC76-2]  120.99 79.42 90 top
FD1  FIDUCIAL MARK~D  [FIDUCIAL_C40M80]  12.39 78.12 0 top
FD2  FIDUCIAL MARK~D  [FIDUCIAL_C40M80]  6.53 19.23 180 bottom
FD3  FIDUCIAL MARK~D  [FIDUCIAL_C40M80]  355.52 19.31 0 top
FD4  FIDUCIAL MARK~D  [FIDUCIAL_C40M80]  359.29 44.87 180 bottom
FD5  FIDUCIAL MARK~D  [FIDUCIAL_C40M80]  279.09 25.14 180 bottom
FD6  FIDUCIAL MARK~D  [FIDUCIAL_C40M80]  156.73 3.66 0 top
FV1  1.5A_65V_T0603FF1500TM  [F_T0603FF1500TM]  134.2 124.13 270 bottom
FZ1  1A_65V_T0603FF1000TM  [F_T0603FF1000TM]  136.64 126.3 180 bottom
FZ2  1A_65V_T0603FF1000TM  [F_T0603FF1000TM]  112.95 143.14 0 top
H1  -  [H_3P2]  392.25 3 0 top
H3  -  [H_3P2]  141.21 121.07 0 top
H4  -  [H_2P8]  109.95 92.8 0 top
H5  -  [H_3P2]  63.25 2.6 0 top
H6  -  [H_2P5]  3.95 46.76 0 top
H7  -  [H_3P7]  263.95 75.27 0 top
H8  -  [H_3P7]  263.95 20.87 0 top
H9  -  [H_3P2]  132.95 172.1 0 top
H11  -  [H_3P2]  295.95 90.8 0 top
H12  -  [H_3P7]  227.85 19.07 0 top
H13  -  [H_3P7]  227.85 76.17 0 top
H14  -  [H_3P2]  403.75 74.03 0 top
H15  -  [H_3P2]  249.95 2.6 0 top
H16  -  [H_2P5]  3.6 62.95 0 top
H17  -  [H_2P8]  324.95 64.8 0 top
H18  -  [H_2P5]  3.95 79.16 0 top
H19  -  [H_2P8]  6.85 41.03 0 top
H20  -  [H_2P0N]  392.25 7 0 top
H21  -  [H_3P2]  120.01 138.36 0 top
H22  -  [H_3P2]  154.48 152.54 0 top
H23  -  [H_2P8X2P0N]  132.97 165.59 328.9 top
JAPS1  ACES_50506-01841-P01  [ACES_50506-01841-P01_18P]  110.97 71.02 270 bottom
JCCG1  ACES_50521-01041-P01  [ACES_50521-01041-P01_10P]  22.33 44.7 180 bottom
JDEG1  JXT_FP241AH-010GAAM  [JXT_FP241AH-010GAAM_10P]  112.38 58.31 270 bottom
JDG1  BELLW_80252-0521  [BELLW_80252-0521_5P-T]  110.4 105.75 90 top
JDGFF1  UNIMI_FBGCAX011  [UNIMI_FBGCAX011_68P-T-S]  239.01 87.52 180 top
JDGFF2  UNIMI_FBGCAX011  [UNIMI_FBGCAX011_68P-T-S]  254.01 87.52 180 top
JDGFF3  UNIMI_FBGCAX011  [UNIMI_FBGCAX011_68P-T-S]  269.01 87.52 180 top
JDGFF4  UNIMI_FBGCAX011  [UNIMI_FBGCAX011_68P-T-S]  284.01 87.52 180 top
JDIMM1  ADDR0208-P001A02  [LOTES_ADDR0208-P001A_260P]  173.67 15.73 270 bottom
JDIMM2  BELLW_80888-2021  [BELLW_80888-2021_260P-T]  181.87 15.73 90 top
JDIMM3  BELLW_80888-2021  [BELLW_80888-2021_260P-T]  187.39 15.72 90 bottom
JDIMM4  ADDR0206-P001A02  [LOTES_ADDR0208-P001A_260P]  195.59 15.73 270 top
JEDP1  ACES_50398-04041-001  [ACES_50398-04041-001_40P]  113.2 118.91 0 top
JESPI  JXT_FP241AH-010GAAM  [JXT_FP241AH-010GAAM_10P]  100.33 15.2 180 bottom
JFAN1  ACES_50271-0040N-001  [ACES_50271-0040N-001_4P]  115.43 74.64 240.6 top
JFAN2  ACES_50271-0040N-001  [ACES_50271-0040N-001_4P]  306.95 73.1 90 top
JHP1  SINGA_2SJ3088-025111F  [SINGA_2SJ3088-025111F_6P-T]  397.75 26 270 top
JIR1  ACES_50228-0067N-001  [ACES_50228-0067N-001_6P]  114.55 132.8 0 top
JKBTP1  CVILU_CF2020FV0RK-NH  [CVILU_CF2020FV0RK-NH_20P]  13.34 3.07 0 top
JLED1  CVILU_CF2006FV0RK-NH  [CVILU_CF2006FV0RK-NH_6P]  400.5 11.15 0 top
JLOM1  SANTA_130456-911  [SANTA_130456-911_13P-T]  142.18 162.92 180 top
JNGFF1  BELLW_80148-4221  [BELLW_80148-4221_67P]  110.75 104.83 0 bottom
JNGFF2  LOTES_APCI0071-P001A  [LOTES_APCI0071-P001A_67P]  145.24 107.01 0 bottom
JNGFF3  BELLW_SD-80159-4221  [BELLW_SD-80159-4221_67P-T]  319.42 32.04 270 bottom
JNGFF4  LOTES_AP-APCI0356-P001A~D  [LOTES_AP-APCI0356-P001A_75P]  384.25 10.05 180 bottom
JNGFF5  BELLW_SD-80159-4221  [BELLW_SD-80159-4221_67P-T]  318.85 57.35 270 bottom
JNGFF6  BELLW_SD-80159-4221  [BELLW_SD-80159-4221_67P-T]  139.28 97.53 180 bottom
JPB1  HRS_TF31-6S-0P5SH  [HRS_TF31-6S-0P5SH_6P-T]  372.9 45.95 180 top
JRTC1  ACES_50271-0020N-001  [ACES_50271-0020N-001_2P]  293.65 26.2 0 bottom
JSD1  T-SOL_156-1110302600  [T-SOL_156-1110302600_19P]  31.22 16.9 270 top
JSIM1  T-SOL_159-1201300600  [T-SOL_159-1201300600_8P]  127 158.84 180 bottom
JSPI1  ACES_50559-02001-001  [ACES_50559-02001-001_20P]  93.42 21.29 0 bottom
JSPK1  ACES_50271-0060N-001  [ACES_50271-0060N-001_6P-T]  343.16 4.66 90 top
JTAG1  @SHORT PADS~D  [SHORTPADS]  152.73 73.17 0 bottom
JUSB1  SINGA_2UB1593-120111F~D  [SINGA_2UB1593-120111F_9P]  396.42 58.5 90 top
JUSB2  SINGA_2UB1593-120111F~D  [SINGA_2UB1593-120111F_9P]  396.42 33.55 90 top
JUSB3  ACON_TCR2C-9U1U91  [ACON_TCR2C-9U1U91_9P-T]  123.12 164.5 180 top
JUSBC1  FOX_UT12113-1160D-7H~D  [FOX_UT12113-1160D-7H_48P]  7.45 57.48 90 top
JUSH1  HRS_TF31C-26S-0P5SH-800  [HRS_TF31C-26S-0P5SH-800_26P-T]  335.45 46.55 90 top
JXDP1  JXT_FP270H-061G1AM  [JXT_FP270H-061G1AM_61P]  256.28 15.65 180 bottom
L1  MCM1012B900F06BP_4P  [INPAQ_MCM1012B900F06BP_4P]  111.58 100.67 90 bottom
LA6  BLM15PX330SN1D_2P  [MURAT_BLM15PX330SN1D_2P]  346.24 20.99 270 top
LA7  BLM15PX330SN1D_2P  [MURAT_BLM15PX330SN1D_2P]  345.35 20.99 270 top
LA8  BLM15PX330SN1D_2P  [MURAT_BLM15PX330SN1D_2P]  350.12 21.05 270 top
LA9  BLM15PX330SN1D_2P  [MURAT_BLM15PX330SN1D_2P]  349.07 21.05 270 top
LA10  BLM15PX330SN1D_2P  [MURAT_BLM15PX330SN1D_2P]  390.68 17.67 0 bottom
LA11  BLM15PX330SN1D_2P  [MURAT_BLM15PX330SN1D_2P]  390.68 15.89 0 bottom
LA12  BLM15PX600SN1D_2P  [MURAT_BLM15PX600SN1D_2P]  376.64 26.35 270 top
LA14  BLM15PX600SN1D_2P  [MURAT_BLM15PX600SN1D_2P]  374.68 20.21 0 top
LA15  BLM15PX330SN1D_2P  [MURAT_BLM15PX330SN1D_2P]  391.75 25.54 0 bottom
LA16  BLM15PX330SN1D_2P  [MURAT_BLM15PX330SN1D_2P]  391.49 23.13 0 bottom
LA21  HCB2012VF-601T20_2P  [TAI-T_HCB2012VF-601T20_2P]  379.57 28.77 90 top
LA27  BLM15PX600SN1D_2P  [MURAT_BLM15PX600SN1D_2P]  383.13 31.91 180 top
LC1  BLM15GA750SN1D_2P  [MURAT_BLM15GA750SN1D_2P]  119.04 44.51 0 bottom
LC2  BLM15GA750SN1D_2P  [MURAT_BLM15GA750SN1D_2P]  149.17 50.31 180 bottom
LC3  BLM15GA750SN1D_2P  [MURAT_BLM15GA750SN1D_2P]  146.65 47.41 180 bottom
LC562  BLM18EG221TN1D_2P~D  [MURAT_BLM18EG221SN1D_2P]  266.52 68 180 top
LGA1  -  [LNG2DMTR_LGA12_2X2]  305.08 23.24 0 bottom
LH421  LQM18PN2R2NC0L_2P~D  [MURAT_BLM18EG221SN1D_2P]  145.55 59.7 270 top
LH423  LQM18PN2R2NC0L_2P~D  [MURAT_BLM18EG221SN1D_2P]  145.13 16.05 90 top
LI3  MCM1012B900F06BP_4P  [INPAQ_MCM1012B900F06BP_4P]  387.06 63.47 180 top
LI4  MCM1012B900F06BP_4P  [INPAQ_MCM1012B900F06BP_4P]  386.93 36.48 180 top
LI7  MCM1012B900F06BP_4P  [INPAQ_MCM1012B900F06BP_4P]  119.98 155.59 270 top
LI16  DLW21HN900HQ2L_4P  [MURAT_DLW21HN900HQ2L_4P]  152.67 103.24 270 bottom
LI17  DLW21HN900HQ2L_4P  [MURAT_DLW21HN900HQ2L_4P]  154.32 103.24 270 bottom
LL1  4.7UH_MPB201210T-4R7M-NA2_20%  [CHILI_MPB201210T-4R7M-NA2_2P]  158.85 138.97 0 top
LR1  2.2UH_HPC252012NF-2R2M_1.3A_20%  [TAI-T_HPC252012NF-2R2M_2P]  13.42 21.83 180 bottom
LT2  1UH_LQM18PN1R0MFHD_20%  [MURAT_LQM18PN1R0MFHD_2P]  25.06 57.68 90 bottom
LT10  0.6UH_MND-04ABIR60M-XGL_20%  [MAG_MND-04ABIR60M-XGL_2P]  34.57 56.76 90 bottom
LV1  BLM15PX221SN1D_2P  [MURAT_BLM15PX221SN1D_2P]  124.24 116.3 0 top
LV2  MCM1012B900F06BP_4P  [INPAQ_MCM1012B900F06BP_4P]  129.87 113.65 90 top
LV4  BLM18KG331SN1D_2P  [MURAT_BLM18KG331SN1D_2P]  58.27 54.12 90 top
LV5  BLM18KG331SN1D_2P  [MURAT_BLM18KG331SN1D_2P]  49.58 54.66 90 bottom
LV6  BLM18KG331SN1D_2P  [MURAT_BLM18KG331SN1D_2P]  60.78 42.64 270 bottom
LV7  BLM18KG331SN1D_2P  [MURAT_BLM18KG331SN1D_2P]  52.8 56.7 0 top
LV8  BLM18KG331SN1D_2P  [MURAT_BLM18KG331SN1D_2P]  52.89 42.01 0 top
LV9  BLM18KG331SN1D_2P  [MURAT_BLM18KG331SN1D_2P]  69.77 46.48 270 top
LV10  BLM18KG331SN1D_2P  [MURAT_BLM18KG331SN1D_2P]  85.54 56.34 90 top
LV11  BLM18KG331SN1D_2P  [MURAT_BLM18KG331SN1D_2P]  67.76 46.51 270 bottom
LV12  BLM18KG331SN1D_2P  [MURAT_BLM18KG331SN1D_2P]  71.54 57.79 180 top
LV13  BLM18KG331SN1D_2P  [MURAT_BLM18KG331SN1D_2P]  67.68 54.38 90 bottom
NOREF  -  []  295.95 90.8 0 top
NOREF#2  -  []  63.25 2.6 0 top
NOREF#3  -  []  227.85 76.17 0 top
NOREF#4  -  []  3.95 79.16 0 top
NOREF#5  -  []  63.25 2.6 0 top
NOREF#6  -  []  263.95 20.87 0 top
NOREF#7  -  []  233.6 90.34 0 top
NOREF#8  -  []  154.48 152.54 0 top
NOREF#9  -  []  186.85 8.06 0 top
NOREF#10  -  []  141.21 121.07 0 top
NOREF#11  -  []  213.51 70.3 0 top
NOREF#12  -  []  132.95 172.1 0 top
NOREF#13  -  []  324.95 64.8 0 top
NOREF#14  -  []  214.82 56.91 270 top
NOREF#15  -  []  278.6 90.34 0 top
NOREF#16  -  []  263.6 90.34 0 top
NOREF#17  -  []  227.85 19.07 0 top
NOREF#18  -  []  3.95 46.76 0 top
NOREF#19  -  []  204.93 3.62 0 top
NOREF#20  -  []  392.26 3 0 top
NOREF#21  -  []  173.89 3.27 0 top
NOREF#22  -  []  120.01 138.36 0 top
NOREF#23  -  []  392.25 7 0 top
NOREF#24  -  []  109.95 92.8 0 top
NOREF#25  -  []  6.85 41.03 0 top
NOREF#26  -  []  249.95 2.6 0 top
NOREF#27  -  []  3.6 62.96 0 top
NOREF#28  -  []  105.26 219.57 0 top
NOREF#29  -  []  403.75 74.03 0 top
NOREF#30  -  []  263.95 75.27 0 top
NOREF#31  -  []  248.6 90.34 0 top
NOREF#32  -  []  191.87 -33.55 0 top
NOREF#33  -  []  214.07 19.32 90 bottom
NOREF#34  -  []  142.69 148.8 180 bottom
NOREF#35  -  []  221.26 5.39 180 bottom
NOREF#36  -  []  218.16 68.11 180 bottom
NOREF#37  -  []  147.91 5.5 180 bottom
PBATT1  DEREN_40-42251-01001RHF  [DEREN_40-42251-01001RHF_10P-T]  63.9 12.63 0 bottom
PC1  0.022U_0603_50V7K  [C_0603]  90.33 25.99 180 top
PC2  1000P_0402_50V7K  [C_0402]  96.15 63.67 180 bottom
PC3  1500P_0402_50V7K  [C_0402]  82.63 23.74 180 top
PC4  1000P_0402_50V7K  [C_0402]  97.81 51.07 180 bottom
PC5  0.1U_0402_10V7K  [C_0402]  85.36 17.39 180 top
PC6  0.1U_0402_25V6  [C_0402]  85.37 21.66 0 top
PC7  100P_0402_50V8J  [C_0402]  9.93 47.64 180 bottom
PC8  1000P_0402_50V7K  [C_0402]  9.93 48.66 180 bottom
PC9  0.1U_0603_25V7K  [C_0603]  12.27 42.24 270 bottom
PC10  100P_0402_50V8J  [C_0402]  14.15 41.72 270 bottom
PC11  0.022U_0603_50V7K  [C_0603]  47.71 29.64 270 top
PC12  1500P_0402_50V7K  [C_0402]  57.52 30.06 270 top
PC13  0.1U_0402_25V6  [C_0402]  56.7 27.21 270 top
PC14  100P_0402_50V8J  [C_0402]  22.02 67.54 45 top
PC15  1000P_0402_50V7K  [C_0402]  21.37 68.21 45 top
PC16  0.1U_0603_25V7K  [C_0603]  25.56 63.02 45 top
PC17  100P_0402_50V8J  [C_0402]  24.66 64.68 45 top
PC18  0.022U_0603_50V7K  [C_0603]  47.44 33.48 270 bottom
PC19  1500P_0402_50V7K  [C_0402]  60.14 30.06 270 bottom
PC20  0.1U_0402_25V6  [C_0402]  54.43 30.19 270 bottom
PC21  0.1U_0603_25V7K  [C_0603]  117.03 91.99 180 top
PC22  10U_0805_25V6K  [C_0805]  117.38 90.39 180 top
PC23  100U_D3L_25VM_R60M  [C_T521D107M025ATE060]  120.66 85.63 0 top
PC24  4.7U_0402_6.3V6M  [C_0402]  300.45 29.05 270 bottom
PC25  2200P_0402_50V7K  [C_0402]  71.31 10.99 0 top
PC30  82P_0402_50V8J  [C_0402]  116.75 89.04 180 top
PC100  0.1U_0402_25V6  [C_0402]  140.46 114.31 90 bottom
PC101  22U_0603_6.3V6M  [C_0603]  139.02 102.14 270 top
PC102  22U_0603_6.3V6M  [C_0603]  140.22 102.14 270 top
PC103  22U_0603_6.3V6M  [C_0603]  141.44 102.14 270 top
PC104  22U_0603_6.3V6M  [C_0603]  141.44 102.14 270 bottom
PC105  22U_0603_6.3V6M  [C_0603]  140.22 102.14 270 bottom
PC106  22U_0603_6.3V6M  [C_0603]  139.02 102.14 270 bottom
PC107  10U_0805_25V6K  [C_0805]  137.65 113.2 90 bottom
PC108  10U_0805_25V6K  [C_0805]  139.14 114.45 90 top
PC109  680P_0402_50V7K  [C_0402]  139.89 105.37 0 top
PC110  0.1U_0603_25V7K  [C_0603]  140.31 110.81 180 top
PC111  2200P_0402_50V7K  [C_0402]  140.46 114.31 90 top
PC112  1000P_0402_50V7K  [C_0402]  132.63 112.81 180 top
PC113  4.7U_0402_6.3V6M  [C_0402]  132.67 110.1 180 top
PC114  0.1U_0402_25V6  [C_0402]  57.62 8.69 270 bottom
PC115  0.1U_0603_25V7K  [C_0603]  50.78 12.04 270 bottom
PC116  2200P_0402_50V7K  [C_0402]  57.61 8.69 270 top
PC117  10U_0805_25V6K  [C_0805]  56.29 9.64 270 bottom
PC118  10U_0805_25V6K  [C_0805]  56.3 9.64 270 top
PC119  4.7U_0402_6.3V6M  [C_0402]  49.75 4.51 270 bottom
PC120  22U_0603_6.3V6M  [C_0603]  43.42 4.41 270 bottom
PC121  22U_0603_6.3V6M  [C_0603]  42.02 4.41 270 bottom
PC122  22U_0603_6.3V6M  [C_0603]  40.63 4.41 270 bottom
PC123  22U_0603_6.3V6M  [C_0603]  40.62 4.41 270 top
PC124  22U_0603_6.3V6M  [C_0603]  43.41 4.41 270 top
PC125  22U_0603_6.3V6M  [C_0603]  42.02 4.41 270 top
PC126  680P_0402_50V7K  [C_0402]  46.98 12.1 180 top
PC127  4.7U_0402_6.3V6M  [C_0402]  50.94 4.51 270 bottom
PC128  1000P_0402_50V7K  [C_0402]  52.79 4.52 270 bottom
PC129  4.7U_0402_6.3V6M  [C_0402]  53.71 4.52 270 bottom
PC138  82P_0402_50V8J  [C_0402]  57.41 11.25 0 bottom
PC200  10U_0805_25V6K  [C_0805]  124.69 9.58 0 top
PC201  0.22U_0603_10V7K  [C_0603]  116.88 11.45 0 top
PC202  10U_0805_25V6K  [C_0805]  124.69 11.29 0 top
PC203  0.1U_0402_25V6  [C_0402]  125.15 12.62 0 top
PC204  2200P_0402_50V7K  [C_0402]  125.15 13.54 0 top
PC205  22U_0603_6.3V6M  [C_0603]  114.36 16.32 90 top
PC206  4.7U_0402_6.3V6M  [C_0402]  113.09 9.79 0 top
PC207  330U_D2_2VM_R9M  [C_D2]  141.46 10.78 180 top
PC208  0.033U_0402_16V7K  [C_0402]  113.04 16.18 90 top
PC209  4.7U_0402_6.3V6M  [C_0402]  111.83 9.82 270 top
PC210  680P_0402_50V7K  [C_0402]  131.94 8.3 90 top
PC211  220P_0402_50V8J  [C_0402]  109.97 16.96 0 top
PC212  .1U_0402_16V7K  [C_0402]  112.15 16.18 90 top
PC213  4.7U_0402_6.3V6M  [C_0402]  110.05 12.64 180 top
PC300  2200P_0402_50V7K  [C_0402]  315.47 56.59 90 bottom
PC301  680P_0402_50V7K  [C_0402]  301.51 61.86 180 top
PC302  0.1U_0402_25V6  [C_0402]  314.56 56.59 90 bottom
PC303  10U_0805_25V6K  [C_0805]  313.26 56.7 90 top
PC304  10U_0805_25V6K  [C_0805]  313.26 56.7 90 bottom
PC305  0.1U_0603_25V7K  [C_0603]  306.93 54.18 180 top
PC307  22U_0603_6.3V6M  [C_0603]  297.67 60.65 90 bottom
PC308  22U_0603_6.3V6M  [C_0603]  298.89 60.65 90 bottom
PC309  22U_0603_6.3V6M  [C_0603]  297.67 60.65 90 top
PC310  22U_0603_6.3V6M  [C_0603]  298.89 60.65 90 top
PC312  0.1U_0402_25V6  [C_0402]  308.91 61.5 90 top
PC313  4.7U_0402_6.3V6M  [C_0402]  308.53 56.87 0 bottom
PC314  82P_0402_50V8J  [C_0402]  309.37 54.59 270 top
PC400  10U_0603_6.3V6M  [C_0603]  155.7 91.33 0 top
PC401  0.1U_0402_16V7K  [C_0402]  157.82 94.97 90 top
PC402  68P_0402_50V8J  [C_0402]  156.85 95.91 270 top
PC403  22U_0603_6.3V6M  [C_0603]  165.64 89.41 270 bottom
PC404  22U_0603_6.3V6M  [C_0603]  164.65 94.86 0 top
PC405  680P_0402_50V7K  [C_0402]  161.64 89.83 0 top
PC406  10U_0603_6.3V6M  [C_0603]  155.74 89.82 0 top
PC500  0.1U_0402_25V6  [C_0402]  348.62 43.08 270 top
PC501  0.1U_0603_25V7K  [C_0603]  356.82 46.64 270 top
PC502  2200P_0402_50V7K  [C_0402]  347.7 43.1 270 top
PC503  10U_0805_25V6K  [C_0805]  351.7 43.96 270 top
PC504  10U_0805_25V6K  [C_0805]  349.95 43.98 270 top
PC505  4.7U_0402_6.3V6M  [C_0402]  357.26 39.17 270 top
PC506  22U_0603_6.3V6M  [C_0603]  367.98 42.93 90 top
PC507  22U_0603_6.3V6M  [C_0603]  367.97 40.77 270 top
PC508  22U_0603_6.3V6M  [C_0603]  369.19 40.77 270 top
PC509  22U_0603_6.3V6M  [C_0603]  370.43 40.77 270 top
PC510  22U_0603_6.3V6M  [C_0603]  369.29 42.93 90 top
PC511  22U_0603_6.3V6M  [C_0603]  370.56 42.93 90 top
PC512  680P_0402_50V7K  [C_0402]  363.29 47.81 0 top
PC513  4.7U_0402_6.3V6M  [C_0402]  355.98 39.19 270 top
PC514  1000P_0402_50V7K  [C_0402]  354.14 39.03 270 top
